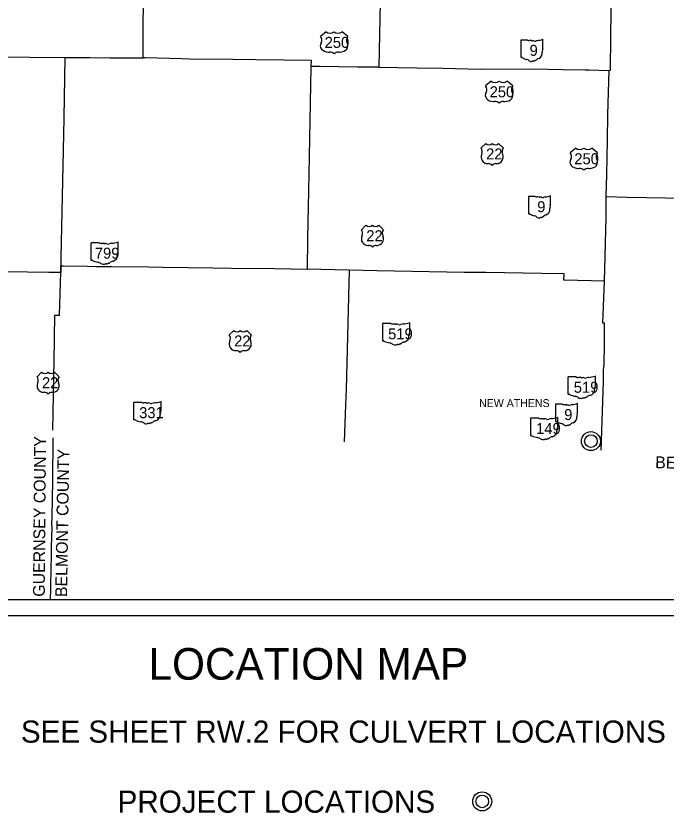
# Model space of a CAD drawing. Extents: x 0 to 70.6, y 0 to 31.9.
# Drawn here: x 3.59 to 7.7, y 12.75 to 17.79 of the extents above; entities that cross this region are included whole.
import ezdxf

# ---------------------------------------------------------------- set-up
doc = ezdxf.new("R2010")
doc.units = 0
for name, color, linetype in [('GM_X_Adjacent_County', 7, 'Continuous'), ('GM_X_County_Road', 7, 'Continuous'), ('GM_X_County_Road_Text', 7, 'Continuous'), ('GM_X_County_ROW', 7, 'Continuous'), ('GM_X_Minor_Lake_Text', 7, 'Continuous'), ('GM_X_Minor_River', 7, 'Continuous'), ('GM_X_Minor_River_Text', 7, 'Continuous'), ('GM_X_Township', 7, 'Continuous')]:
    doc.layers.add(name, color=color, linetype=linetype)

msp = doc.modelspace()

# ---------------------------------------------------------------- linework, layer by layer
at = {"layer": 'GM_X_Adjacent_County'}
for centre, radius in [((7.2238, 15.1012), 0.06), ((7.2238, 15.1012), 0.04), ((6.5363, 12.8249), 0.06), ((6.5363, 12.8249), 0.04)]:
    msp.add_circle(centre, radius, dxfattribs=at)
at = {"layer": 'GM_X_County_Road_Text'}
msp.add_lwpolyline([(3.8222, 15.1223), (3.819, 14.8502), (3.8155, 14.6248), (3.8154, 14.617), (3.8142, 14.5801), (3.8147, 14.5539), (3.8122, 14.4308), (3.8104, 14.3615), (3.8091, 14.3107), (3.8066, 14.1687), (3.8059, 14.1)], dxfattribs=at)
at = {"layer": 'GM_X_County_ROW'}
for points in [[(7.321, 16.6464), (7.3246, 16.7855), (7.3288, 17.0034), (7.3306, 17.1648), (7.3383, 17.4443), (7.3468, 17.4448), (7.3472, 17.4976), (7.3491, 17.6075), (7.3489, 17.6421), (7.3523, 17.8325), (7.3534, 17.89), (7.3544, 17.9622), (7.3569, 18.1501), (7.3595, 18.2961), (7.3593, 18.3311), (7.3616, 18.5061), (7.3799, 18.5061), (7.6271, 18.5028), (7.8521, 18.4984), (8.053, 18.4945), (8.318, 18.489), (8.6937, 18.4775)], [(5.8906, 17.8717), (5.8866, 17.6728), (5.8829, 17.4634), (5.8599, 17.4636), (5.8264, 17.464), (5.749, 17.4649), (5.5121, 17.4676), (5.4556, 17.4682), (5.4565, 17.507), (5.1048, 17.5102), (4.9592, 17.5125), (4.6867, 17.5154), (4.6367, 17.5167), (4.4077, 17.5227), (4.393, 17.5228), (4.3934, 17.5648), (4.3922, 17.686), (4.3981, 18.1307)], [(3.0949, 17.5353), (3.2293, 17.5323), (3.8985, 17.5257), (3.8919, 17.1438), (3.8881, 16.9409), (3.8731, 16.2595), (3.8722, 16.2095), (3.8718, 16.1664), (3.7972, 16.1673), (3.5262, 16.1717), (3.5138, 16.1718), (3.2094, 16.1759), (2.6123, 16.1864), (2.2906, 16.1846), (2.2448, 16.1852)], [(3.8985, 17.5257), (3.9008, 17.5256), (4.0551, 17.5249), (4.1816, 17.5239), (4.393, 17.5228)], [(7.3099, 16.1124), (7.056, 16.1177), (7.0526, 16.1178), (7.0541, 16.1579), (6.9134, 16.1605), (6.5592, 16.1659), (6.4234, 16.1677), (5.8693, 16.178), (5.6952, 16.1822), (5.4311, 16.189), (5.4351, 16.3751), (5.4369, 16.4874), (5.44, 16.683), (5.4471, 17.0111), (5.4556, 17.4682)], [(5.8829, 17.4634), (6.1235, 17.4605), (6.2881, 17.4575), (6.5279, 17.4525), (6.8541, 17.4534), (7.0492, 17.4506), (7.1868, 17.4473), (7.2109, 17.4467), (7.3383, 17.4443)], [(7.2893, 15.0436), (7.3033, 15.4757), (7.3037, 15.5437), (7.3048, 15.5766), (7.3083, 15.5766), (7.3085, 15.7229), (7.3089, 15.8467), (7.2997, 15.8465), (7.3099, 16.1124), (7.3135, 16.2675), (7.3192, 16.5173), (7.3208, 16.6423), (7.321, 16.6464), (7.4531, 16.644), (7.8197, 16.6369), (8.1172, 16.6295), (8.1959, 16.6272), (8.2442, 16.6261), (8.3923, 16.6227), (8.6528, 16.6128)], [(3.8226, 15.1709), (3.828, 15.5021), (3.8281, 15.5136), (3.8294, 15.6037), (3.8339, 15.8974), (3.8649, 15.897), (3.8718, 16.1664), (3.8722, 16.2095), (3.8872, 16.2093), (4.0414, 16.2069), (4.0954, 16.205), (4.1927, 16.2038), (4.4267, 16.2021), (4.5177, 16.2007), (4.8334, 16.1961), (4.9511, 16.1945), (5.2258, 16.1916), (5.4311, 16.189)], [(5.6952, 16.1822), (5.6755, 15.4295), (5.6732, 15.3284), (5.6632, 15.0971)]]:
    msp.add_lwpolyline(points, dxfattribs=at)
at = {"layer": 'GM_X_Minor_Lake_Text'}
for p, q in [((5.5495, 17.6878), (5.5132, 17.6588)), ((5.6872, 17.6588), (5.651, 17.6878)), ((5.564, 17.5602), (5.5712, 17.5602)), ((5.6292, 17.5602), (5.6365, 17.5602)), ((6.5927, 17.3754), (6.5565, 17.3464)), ((6.7305, 17.3464), (6.6942, 17.3754)), ((6.6072, 17.2478), (6.6145, 17.2478)), ((6.6725, 17.2478), (6.6797, 17.2478)), ((6.559, 16.9828), (6.53, 16.9538)), ((6.6692, 16.9538), (6.6402, 16.9828)), ((7.128, 16.9524), (7.0917, 16.9233)), ((7.2657, 16.9233), (7.2295, 16.9524)), ((6.5706, 16.8552), (6.5764, 16.8552)), ((6.6228, 16.8552), (6.6286, 16.8552)), ((7.1425, 16.8247), (7.1497, 16.8247)), ((7.2077, 16.8247), (7.215, 16.8247)), ((5.8017, 16.466), (5.7727, 16.437)), ((5.9119, 16.437), (5.8829, 16.466)), ((5.8133, 16.3384), (5.8191, 16.3384)), ((5.8655, 16.3384), (5.8713, 16.3384)), ((4.9662, 15.8012), (4.9372, 15.7721)), ((5.0764, 15.7721), (5.0474, 15.8012)), ((4.9778, 15.6735), (4.9836, 15.6735)), ((5.03, 15.6735), (5.0358, 15.6735)), ((3.7513, 15.5374), (3.7223, 15.5084)), ((3.8615, 15.5084), (3.8325, 15.5374)), ((3.7629, 15.4098), (3.7687, 15.4098)), ((3.8151, 15.4098), (3.8209, 15.4098))]:
    msp.add_line(p, q, dxfattribs=at)
for centre, radius, start, end in [((6.5793, 17.0035), 0.029, 225.573, 314.427), ((6.6199, 17.0035), 0.029, 225.573, 314.427), ((6.4967, 16.9305), 0.0406, 334.5471, 35.0009), ((6.7024, 16.9305), 0.0406, 144.9991, 205.4529), ((6.5701, 16.8958), 0.0406, 154.8319, 270.6383), ((6.629, 16.8958), 0.0406, 269.3617, 25.1681), ((6.5764, 16.8261), 0.029, 36.8699, 90), ((6.6228, 16.8261), 0.029, 90, 143.1301), ((5.7394, 16.4137), 0.0406, 334.5471, 35.0009), ((5.822, 16.4867), 0.029, 225.573, 314.427), ((5.8626, 16.4867), 0.029, 225.573, 314.427), ((5.9452, 16.4137), 0.0406, 144.9991, 205.4529), ((5.8129, 16.379), 0.0406, 154.8319, 270.6383), ((5.8718, 16.379), 0.0406, 269.3617, 25.1681), ((5.8191, 16.3094), 0.029, 36.8699, 90), ((5.8655, 16.3094), 0.029, 90, 143.1301), ((4.9039, 15.7489), 0.0406, 334.5471, 35.0009), ((4.9865, 15.8219), 0.029, 225.573, 314.427), ((5.0271, 15.8219), 0.029, 225.573, 314.427), ((5.1096, 15.7489), 0.0406, 144.9991, 205.4529), ((4.9773, 15.7141), 0.0406, 154.8319, 270.6383), ((5.0362, 15.7141), 0.0406, 269.3617, 25.1681), ((4.9836, 15.6445), 0.029, 36.8699, 90), ((5.03, 15.6445), 0.029, 90, 143.1301), ((3.7716, 15.5581), 0.029, 225.573, 314.427), ((3.8122, 15.5581), 0.029, 225.573, 314.427), ((3.7625, 15.4504), 0.0406, 154.8319, 270.6383), ((3.6891, 15.4851), 0.0406, 334.5471, 35.0009), ((3.8214, 15.4504), 0.0406, 269.3617, 25.1681), ((3.8948, 15.4851), 0.0406, 144.9991, 205.4529), ((3.7687, 15.3808), 0.029, 36.8699, 90), ((3.8151, 15.3808), 0.029, 90, 143.1301)]:
    msp.add_arc(centre, radius, start, end, dxfattribs=at)
for centre, major_axis, start_param, end_param in [((5.5749, 17.7085), (-0.0363, 0), 0.795399, 2.346194), ((5.6256, 17.7085), (-0.0363, 0), 0.795399, 2.346194), ((5.4716, 17.6355), (0.0508, 0), 5.838949, 6.894067), ((5.7288, 17.6355), (-0.0508, 0), 5.672304, 6.727422), ((5.5634, 17.6008), (0.0508, 0), 2.702327, 4.723529), ((5.6371, 17.6008), (-0.0508, 0), 1.559657, 3.580859), ((5.5712, 17.5312), (-0.0363, 0), 3.785094, 4.712389), ((5.6292, 17.5312), (-0.0363, 0), 4.712389, 5.639684), ((6.5149, 17.3231), (0.0508, 0), 5.838949, 6.894067), ((6.6181, 17.3961), (-0.0363, 0), 0.795399, 2.346194), ((6.6688, 17.3961), (-0.0363, 0), 0.795399, 2.346194), ((6.7721, 17.3231), (-0.0508, 0), 5.672304, 6.727422), ((6.6066, 17.2884), (0.0508, 0), 2.702327, 4.723529), ((6.6803, 17.2884), (-0.0508, 0), 1.559657, 3.580859), ((6.6145, 17.2188), (-0.0363, 0), 3.785094, 4.712389), ((6.6725, 17.2188), (-0.0363, 0), 4.712389, 5.639684), ((7.1534, 16.9731), (-0.0363, 0), 0.795399, 2.346194), ((7.2041, 16.9731), (-0.0363, 0), 0.795399, 2.346194), ((7.1419, 16.8653), (0.0508, 0), 2.702327, 4.723529), ((7.0501, 16.9001), (0.0508, 0), 5.838949, 6.894067), ((7.2155, 16.8653), (-0.0508, 0), 1.559657, 3.580859), ((7.3073, 16.9001), (-0.0508, 0), 5.672304, 6.727422), ((7.1497, 16.7957), (-0.0363, 0), 3.785094, 4.712389), ((7.2077, 16.7957), (-0.0363, 0), 4.712389, 5.639684)]:
    msp.add_ellipse(centre, major_axis=major_axis, ratio=0.8, start_param=start_param, end_param=end_param, dxfattribs=at)
at = {"layer": 'GM_X_Minor_River_Text'}
for p, q in [((6.7815, 17.6342), (6.7815, 17.5285)), ((6.8236, 17.636), (6.7829, 17.636)), ((6.9207, 17.5833), (6.9207, 17.6386)), ((6.9207, 17.5833), (6.9207, 17.5833)), ((6.8297, 16.6459), (6.8297, 16.5403)), ((6.8718, 16.6477), (6.831, 16.6477)), ((6.9689, 16.5951), (6.9689, 16.6504)), ((6.9689, 16.5951), (6.9689, 16.5951)), ((4.0616, 16.3524), (4.0616, 16.2468)), ((4.1142, 16.3543), (4.0633, 16.3543)), ((4.2356, 16.3016), (4.2356, 16.3569)), ((4.2356, 16.3016), (4.2356, 16.3016)), ((5.9051, 15.8427), (5.9051, 15.737)), ((5.9578, 15.8445), (5.9069, 15.8445)), ((6.0792, 15.7919), (6.0792, 15.8471)), ((6.0791, 15.7919), (6.0792, 15.7919)), ((7.0786, 15.5052), (7.0786, 15.3996)), ((7.1313, 15.507), (7.0803, 15.507)), ((7.2526, 15.4544), (7.2526, 15.5097)), ((7.2526, 15.4544), (7.2526, 15.4544)), ((4.3321, 15.3446), (4.3321, 15.239)), ((4.3848, 15.3464), (4.3339, 15.3464)), ((4.5062, 15.2938), (4.5062, 15.3491)), ((7.0002, 15.3327), (7.0002, 15.2271)), ((7.0423, 15.3346), (7.0015, 15.3346)), ((7.1394, 15.2819), (7.1394, 15.3372)), ((4.5062, 15.2938), (4.5062, 15.2938)), ((7.1394, 15.2819), (7.1394, 15.2819)), ((6.8408, 15.2445), (6.8408, 15.1389)), ((6.8935, 15.2463), (6.8425, 15.2463)), ((7.0148, 15.1937), (7.0148, 15.249)), ((7.0148, 15.1937), (7.0148, 15.1937))]:
    msp.add_line(p, q, dxfattribs=at)
for centre, radius, start, end in [((6.7831, 17.6344), 0.00161, 98.1301, 188.1301), ((6.8333, 17.6482), 0.0156, 231.6195, 271.1119), ((6.8385, 17.5767), 0.0562, 80.4867, 94.9883), ((6.8513, 17.6349), 0.00451, 219.7921, 297.1024), ((6.8579, 17.6227), 0.00938, 54.4667, 119.1411), ((6.87, 17.6395), 0.0113, 233.8562, 294.8282), ((6.8899, 17.6037), 0.0297, 97.3462, 120.7689), ((6.8711, 17.78), 0.1476, 275.8445, 288.9065), ((6.9192, 17.6388), 0.00155, 351.8621, 97.738), ((6.9203, 17.5793), 0.0024, 107.944, 210.337), ((6.919, 17.5831), 0.00166, 289.6038, 7.7341), ((6.8794, 17.5532), 0.0369, 292.3089, 8.9858), ((6.9262, 17.5602), 0.0105, 136.8065, 186.9296), ((6.9051, 17.5723), 0.0144, 340.033, 23.6496), ((6.7831, 17.5283), 0.00163, 171.9584, 258.3066), ((6.7833, 17.5391), 0.0124, 267.339, 280.6039), ((6.7859, 17.5224), 0.00448, 29.7484, 93.2717), ((6.8424, 17.6173), 0.1066, 240.4129, 257.1985), ((6.8106, 17.481), 0.0334, 47.1842, 75.836), ((6.8467, 17.5219), 0.0212, 230.7004, 286.2918), ((6.8589, 17.4853), 0.0174, 85.6951, 111.2099), ((6.8605, 17.514), 0.0113, 268.777, 315.5493), ((6.8707, 17.5037), 0.00318, 65.7517, 132.6484), ((6.8693, 17.5183), 0.0119, 282.8732, 323.2771), ((6.8949, 17.4988), 0.0202, 94.4031, 142.5768), ((6.8313, 16.6461), 0.00161, 98.1301, 188.1301), ((6.8815, 16.66), 0.0156, 231.6195, 271.1119), ((6.8867, 16.5884), 0.0562, 80.4867, 94.9883), ((6.8994, 16.6467), 0.00451, 219.7921, 297.1024), ((6.9061, 16.6345), 0.00938, 54.4667, 119.1411), ((6.9182, 16.6512), 0.0113, 233.8562, 294.8282), ((6.9381, 16.6155), 0.0297, 97.3462, 120.7689), ((6.9193, 16.7918), 0.1476, 275.8445, 288.9065), ((6.9673, 16.6506), 0.00155, 351.8621, 97.738), ((6.9744, 16.5719), 0.0105, 136.8065, 186.9296), ((6.9685, 16.591), 0.0024, 107.944, 210.337), ((6.9533, 16.584), 0.0144, 340.033, 23.6496), ((6.9672, 16.5949), 0.00166, 289.6038, 7.7341), ((6.8313, 16.54), 0.00163, 171.9584, 258.3066), ((6.8315, 16.5508), 0.0124, 267.339, 280.6039), ((6.8341, 16.5342), 0.00448, 29.7484, 93.2717), ((6.8906, 16.6291), 0.1066, 240.4129, 257.1985), ((6.8588, 16.4928), 0.0334, 47.1842, 75.836), ((6.9175, 16.53), 0.0119, 282.8732, 323.2771), ((6.9431, 16.5106), 0.0202, 94.4031, 142.5768), ((6.9276, 16.5649), 0.0369, 292.3089, 8.9858), ((6.8949, 16.5336), 0.0212, 230.7004, 286.2918), ((6.9071, 16.4971), 0.0174, 85.6951, 111.2099), ((6.9087, 16.5257), 0.0113, 268.777, 315.5493), ((6.9189, 16.5155), 0.00318, 65.7517, 132.6484), ((7.0018, 15.333), 0.00161, 98.1301, 188.1301), ((7.052, 15.3468), 0.0156, 231.6195, 271.1119), ((7.0572, 15.2752), 0.0562, 80.4867, 94.9883), ((7.0699, 15.3335), 0.00451, 219.7921, 297.1024), ((7.0766, 15.3213), 0.00938, 54.4667, 119.1411), ((7.0887, 15.3381), 0.0113, 233.8562, 294.8282), ((7.1086, 15.3023), 0.0297, 97.3462, 120.7689), ((7.0898, 15.4786), 0.1476, 275.8445, 288.9065), ((7.1378, 15.3374), 0.00155, 351.8621, 97.738), ((7.1449, 15.2588), 0.0105, 136.8065, 186.9296), ((7.139, 15.2778), 0.0024, 107.944, 210.337), ((7.1238, 15.2709), 0.0144, 340.033, 23.6496), ((7.1377, 15.2817), 0.00166, 289.6038, 7.7341), ((7.0018, 15.2268), 0.00163, 171.9584, 258.3066), ((7.002, 15.2377), 0.0124, 267.339, 280.6039), ((7.0046, 15.221), 0.00448, 29.7484, 93.2717), ((7.0611, 15.3159), 0.1066, 240.4129, 257.1985), ((7.0293, 15.1796), 0.0334, 47.1842, 75.836), ((7.1136, 15.1974), 0.0202, 94.4031, 142.5768), ((7.0981, 15.2517), 0.0369, 292.3089, 8.9858), ((7.0654, 15.2205), 0.0212, 230.7004, 286.2918), ((7.0776, 15.1839), 0.0174, 85.6951, 111.2099), ((7.0792, 15.2125), 0.0113, 268.777, 315.5493), ((7.0894, 15.2023), 0.00318, 65.7517, 132.6484), ((7.088, 15.2168), 0.0119, 282.8732, 323.2771)]:
    msp.add_arc(centre, radius, start, end, dxfattribs=at)
for centre, major_axis, start_param, end_param in [((4.0635, 16.3527), (0.00202, 0), 1.712693, 3.28349), ((4.1264, 16.3665), (0.0196, 0), 4.042523, 4.731795), ((4.1328, 16.2949), (0.0702, 0), 1.404758, 1.657858), ((4.1488, 16.3532), (0.00564, 0), 3.836095, 5.185415), ((4.1571, 16.341), (0.0117, 0), 0.950623, 2.079405), ((4.1722, 16.3577), (0.0141, 0), 4.081561, 5.145723), ((4.1971, 16.322), (0.0371, 0), 1.699011, 2.107814), ((4.1736, 16.4983), (0.1845, 0), 4.814394, 5.042369), ((4.2336, 16.3571), (0.00194, 0), 6.141152, 7.989035), ((4.1839, 16.2714), (0.0462, 0), 5.101752, 6.440018), ((4.2425, 16.2785), (0.0131, 0), 2.387724, 3.262537), ((4.2351, 16.2975), (0.003, 0), 1.883978, 3.671073), ((4.216, 16.2906), (0.018, 0), 5.934695, 6.695948), ((4.2335, 16.3014), (0.00207, 0), 5.05454, 6.418171), ((4.0636, 16.2465), (0.00203, 0), 3.00124, 4.508301), ((4.0639, 16.2574), (0.0155, 0), 4.665946, 4.897461), ((4.067, 16.2407), (0.0056, 0), 0.519207, 1.627899), ((4.1377, 16.3356), (0.1333, 0), 4.195997, 4.488961), ((4.098, 16.1993), (0.0417, 0), 0.823519, 1.323587), ((4.1431, 16.2402), (0.0265, 0), 4.026481, 4.996735), ((4.1584, 16.2036), (0.0217, 0), 1.495662, 1.94098), ((4.1603, 16.2322), (0.0141, 0), 4.691044, 5.507374), ((4.173, 16.222), (0.00397, 0), 1.147584, 2.315152), ((4.1714, 16.2365), (0.0149, 0), 4.937069, 5.64225), ((4.2034, 16.2171), (0.0253, 0), 1.647645, 2.488434), ((5.9071, 15.8429), (0.00202, 0), 1.712693, 3.28349), ((5.97, 15.8568), (0.0196, 0), 4.042523, 4.731795), ((5.9764, 15.7852), (0.0702, 0), 1.404758, 1.657858), ((5.9924, 15.8435), (0.00564, 0), 3.836095, 5.185415), ((6.0007, 15.8313), (0.0117, 0), 0.950623, 2.079405), ((6.0158, 15.848), (0.0141, 0), 4.081561, 5.145723), ((6.0407, 15.8122), (0.0371, 0), 1.699011, 2.107814), ((6.0172, 15.9886), (0.1845, 0), 4.814394, 5.042369), ((6.0772, 15.8474), (0.00194, 0), 6.141152, 7.989035), ((6.0275, 15.7617), (0.0462, 0), 5.101752, 6.440018), ((6.0861, 15.7687), (0.0131, 0), 2.387724, 3.262537), ((6.0787, 15.7878), (0.003, 0), 1.883978, 3.671073), ((6.0596, 15.7808), (0.018, 0), 5.934695, 6.695948), ((6.0771, 15.7916), (0.00207, 0), 5.05454, 6.418171), ((5.9072, 15.7368), (0.00203, 0), 3.00124, 4.508301), ((5.9075, 15.7476), (0.0155, 0), 4.665946, 4.897461), ((5.9106, 15.7309), (0.0056, 0), 0.519207, 1.627899), ((5.9813, 15.8259), (0.1333, 0), 4.195997, 4.488961), ((5.9416, 15.6896), (0.0417, 0), 0.823519, 1.323587), ((6.0166, 15.7123), (0.00397, 0), 1.147584, 2.315152), ((6.0149, 15.7268), (0.0149, 0), 4.937069, 5.64225), ((6.047, 15.7074), (0.0253, 0), 1.647645, 2.488434), ((5.9867, 15.7304), (0.0265, 0), 4.026481, 4.996735), ((6.002, 15.6939), (0.0217, 0), 1.495662, 1.94098), ((6.0039, 15.7225), (0.0141, 0), 4.691044, 5.507374), ((7.0806, 15.5054), (0.00202, 0), 1.712693, 3.28349), ((7.1434, 15.5193), (0.0196, 0), 4.042523, 4.731795), ((7.1499, 15.4477), (0.0702, 0), 1.404758, 1.657858), ((7.1659, 15.506), (0.00564, 0), 3.836095, 5.185415), ((7.1741, 15.4938), (0.0117, 0), 0.950623, 2.079405), ((7.1893, 15.5105), (0.0141, 0), 4.081561, 5.145723), ((7.2142, 15.4748), (0.0371, 0), 1.699011, 2.107814), ((7.1907, 15.6511), (0.1845, 0), 4.814394, 5.042369), ((7.2507, 15.5099), (0.00194, 0), 6.141152, 7.989035), ((7.201, 15.4242), (0.0462, 0), 5.101752, 6.440018), ((7.2596, 15.4313), (0.0131, 0), 2.387724, 3.262537), ((7.2522, 15.4503), (0.003, 0), 1.883978, 3.671073), ((7.2331, 15.4433), (0.018, 0), 5.934695, 6.695948), ((7.2506, 15.4542), (0.00207, 0), 5.05454, 6.418171), ((7.0806, 15.3993), (0.00203, 0), 3.00124, 4.508301), ((7.0809, 15.4101), (0.0155, 0), 4.665946, 4.897461), ((7.0841, 15.3935), (0.0056, 0), 0.519207, 1.627899), ((7.1548, 15.4884), (0.1333, 0), 4.195997, 4.488961), ((7.115, 15.3521), (0.0417, 0), 0.823519, 1.323587), ((7.1601, 15.3929), (0.0265, 0), 4.026481, 4.996735), ((7.1754, 15.3564), (0.0217, 0), 1.495662, 1.94098), ((7.1774, 15.385), (0.0141, 0), 4.691044, 5.507374), ((7.1901, 15.3748), (0.00397, 0), 1.147584, 2.315152), ((7.1884, 15.3893), (0.0149, 0), 4.937069, 5.64225), ((7.2205, 15.3699), (0.0253, 0), 1.647645, 2.488434), ((4.3341, 15.3448), (0.00202, 0), 1.712693, 3.28349), ((4.397, 15.3587), (0.0196, 0), 4.042523, 4.731795), ((4.4034, 15.2871), (0.0702, 0), 1.404758, 1.657858), ((4.4194, 15.3454), (0.00564, 0), 3.836095, 5.185415), ((4.4277, 15.3332), (0.0117, 0), 0.950623, 2.079405), ((4.4428, 15.3499), (0.0141, 0), 4.081561, 5.145723), ((4.4677, 15.3142), (0.0371, 0), 1.699011, 2.107814), ((4.4442, 15.4905), (0.1845, 0), 4.814394, 5.042369), ((4.5042, 15.3493), (0.00194, 0), 6.141152, 7.989035), ((4.4545, 15.2636), (0.0462, 0), 5.101752, 6.440018), ((4.5131, 15.2707), (0.0131, 0), 2.387724, 3.262537), ((4.5057, 15.2897), (0.003, 0), 1.883978, 3.671073), ((4.4866, 15.2827), (0.018, 0), 5.934695, 6.695948), ((4.5041, 15.2936), (0.00207, 0), 5.05454, 6.418171), ((4.3342, 15.2387), (0.00203, 0), 3.00124, 4.508301), ((4.3345, 15.2495), (0.0155, 0), 4.665946, 4.897461), ((4.3376, 15.2329), (0.0056, 0), 0.519207, 1.627899), ((4.4083, 15.3278), (0.1333, 0), 4.195997, 4.488961), ((4.3686, 15.1915), (0.0417, 0), 0.823519, 1.323587), ((4.4137, 15.2323), (0.0265, 0), 4.026481, 4.996735), ((4.429, 15.1958), (0.0217, 0), 1.495662, 1.94098), ((4.4309, 15.2244), (0.0141, 0), 4.691044, 5.507374), ((4.4436, 15.2142), (0.00397, 0), 1.147584, 2.315152), ((4.442, 15.2287), (0.0149, 0), 4.937069, 5.64225), ((4.474, 15.2093), (0.0253, 0), 1.647645, 2.488434), ((6.8428, 15.2447), (0.00202, 0), 1.712693, 3.28349), ((6.9056, 15.2586), (0.0196, 0), 4.042523, 4.731795), ((6.9121, 15.187), (0.0702, 0), 1.404758, 1.657858), ((6.928, 15.2453), (0.00564, 0), 3.836095, 5.185415), ((6.9363, 15.2331), (0.0117, 0), 0.950623, 2.079405), ((6.9515, 15.2498), (0.0141, 0), 4.081561, 5.145723), ((6.9764, 15.2141), (0.0371, 0), 1.699011, 2.107814), ((6.9528, 15.3904), (0.1845, 0), 4.814394, 5.042369), ((7.0129, 15.2492), (0.00194, 0), 6.141152, 7.989035), ((6.9632, 15.1635), (0.0462, 0), 5.101752, 6.440018), ((7.0218, 15.1706), (0.0131, 0), 2.387724, 3.262537), ((7.0144, 15.1896), (0.003, 0), 1.883978, 3.671073), ((6.9953, 15.1826), (0.018, 0), 5.934695, 6.695948), ((7.0128, 15.1935), (0.00207, 0), 5.05454, 6.418171), ((6.8428, 15.1386), (0.00203, 0), 3.00124, 4.508301), ((6.8431, 15.1494), (0.0155, 0), 4.665946, 4.897461), ((6.8463, 15.1328), (0.0056, 0), 0.519207, 1.627899), ((6.917, 15.2277), (0.1333, 0), 4.195997, 4.488961), ((6.8772, 15.0914), (0.0417, 0), 0.823519, 1.323587), ((6.9223, 15.1322), (0.0265, 0), 4.026481, 4.996735), ((6.9376, 15.0957), (0.0217, 0), 1.495662, 1.94098), ((6.9395, 15.1243), (0.0141, 0), 4.691044, 5.507374), ((6.9523, 15.1141), (0.00397, 0), 1.147584, 2.315152), ((6.9506, 15.1286), (0.0149, 0), 4.937069, 5.64225), ((6.9826, 15.1092), (0.0253, 0), 1.647645, 2.488434)]:
    msp.add_ellipse(centre, major_axis=major_axis, ratio=0.8, start_param=start_param, end_param=end_param, dxfattribs=at)
at = {"layer": 'GM_X_Township'}
for p, q in [((2.1, 14.1), (8.9, 14.1)), ((2, 14), (9, 14))]:
    msp.add_line(p, q, dxfattribs=at)

# ---------------------------------------------------------------- texts
at = {"layer": 'GM_X_Adjacent_County'}
for s, height, p in [('LOCATION MAP', 0.2, (4.4269, 13.5937)), ('SEE SHEET RW.2 FOR CULVERT LOCATIONS', 0.14, (3.6199, 13.1958)), ('PROJECT LOCATIONS', 0.14, (4.2315, 12.7531))]:
    msp.add_text(s, height=height, dxfattribs=at).set_placement(p)
at = {"layer": 'GM_X_County_Road'}
msp.add_text('NEW ATHENS', height=0.05, rotation=0, dxfattribs=at).set_placement((6.5168, 15.3166))
at = {"layer": 'GM_X_Minor_Lake_Text'}
for s, p in [('250', (5.5404, 17.5863)), ('250', (6.5836, 17.2739)), ('22', (6.561, 16.8813)), ('250', (7.1189, 16.8508)), ('22', (5.8038, 16.3645)), ('22', (4.9682, 15.6996)), ('22', (3.7534, 15.4359))]:
    msp.add_text(s, height=0.06961, dxfattribs=at).set_placement(p)
at = {"layer": 'GM_X_Minor_River'}
for s, rotation, p in [('GUERNSEY COUNTY', 89.57, (3.7713, 14.1179)), ('BELMONT COUNTY', 89.0913, (3.9119, 14.1154)), ('BELMONT COUNTY', 358.3527, (7.6291, 14.931))]:
    msp.add_text(s, height=0.075, rotation=rotation, dxfattribs=at).set_placement(p)
at = {"layer": 'GM_X_Minor_River_Text'}
for s, height, p in [('9', 0.0696, (6.8359, 17.5359)), ('9', 0.0696, (6.884, 16.5477)), ('799', 0.06961, (4.0877, 16.2542)), ('519', 0.06961, (5.9418, 15.7445)), ('519', 0.06961, (7.1153, 15.407)), ('331', 0.06961, (4.3677, 15.2464)), ('9', 0.0696, (7.0545, 15.2345)), ('149', 0.06961, (6.8773, 15.1463))]:
    msp.add_text(s, height=height, dxfattribs=at).set_placement(p)

doc.saveas('drawing.dxf')
